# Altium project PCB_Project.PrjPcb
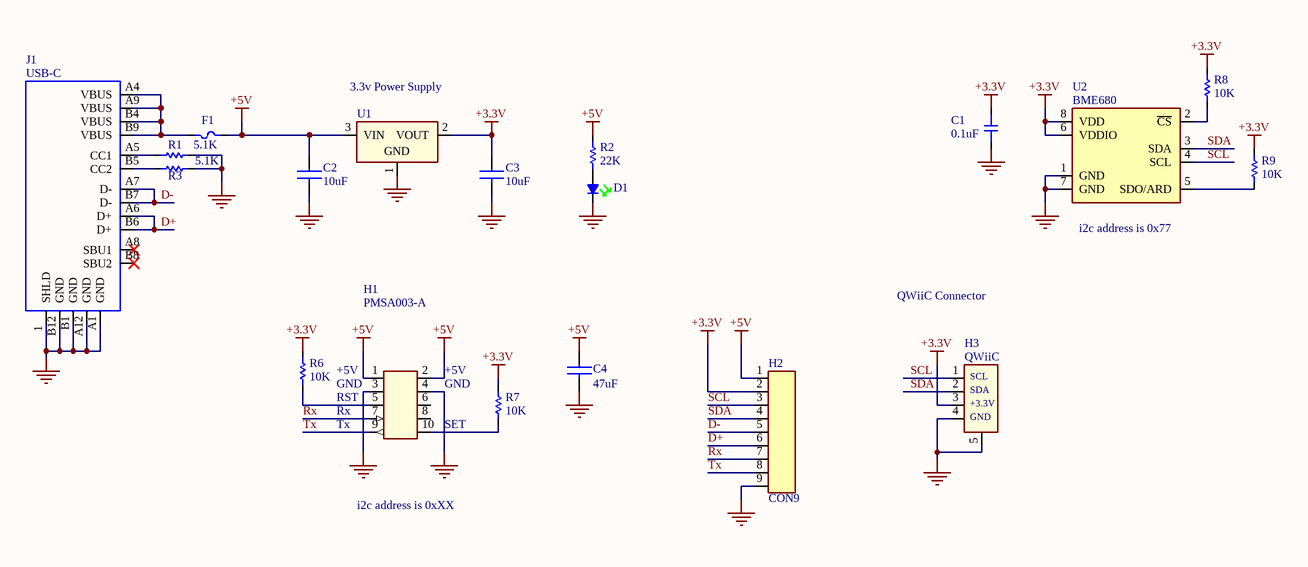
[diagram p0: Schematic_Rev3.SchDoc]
1 sheet, 19 parts. Net scope: global (net labels, ports and power ports of the same name join across sheets).
Board file: PCB_Rev3.PcbDoc

## Sheet Schematic_Rev3.SchDoc: ESP32 Particle Sensor, Sensor
size Tabloid; Organization: .; Address1: @mikerankin; Address2: .; Address3: .; Address4: .; DocumentNumber: .; Revision: 3; SheetNumber: 1; SheetTotal: 1

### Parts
C1  0.1uF  [CAPC1005X56N]
C2  10uF  [CAPC2012X140N]
C3  10uF  [CAPC2012X140N]
C4  47uF  [CAPC3225X160N]
D1  Green Led  [LED1005X40N-Green]  (value not drawn)
F1  TLC-PSMD050  [PTC2012X70L]  (value not drawn)
H1  PMSA003-A  [PMSA003-A]
H2  CON9  [HDR9X1-50MIL]  (no BOM)
H3  QWiiC  [SM04B-SRSS-TB]
J1  USB-C  [TYPE-C-31-M-12]
R1  5.1K  [RESC1005X40L (0402 FOOTPRINT)]
R2  22K  [RESC1005X40L (0402 FOOTPRINT)]
R3  5.1K  [RESC1005X40L (0402 FOOTPRINT)]
R6  10K  [RESC1005X40L (0402 FOOTPRINT)]
R7  10K  [RESC1005X40L (0402 FOOTPRINT)]
R8  10K  [RESC1005X40L (0402 FOOTPRINT)]
R9  10K  [RESC1005X40L (0402 FOOTPRINT)]
U1  NCP1117LPST33T3G  [SOT230P700X180-4N]  (value not drawn)
U2  BME680  [LGA3X3-8N]

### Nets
+3.3V: C1.1 C3.1 H2.2 H3.3 R6.2 R7.2 R8.2 R9.2 U1.2(VOUT) U2.6(VDDIO) U2.8(VDD)
+5V: C2.1 C4.1 F1.1 H1.1(+5V) H1.2(+5V) H2.1 R2.2 U1.3(VIN)
GND: C1.2 C2.2 C3.2 C4.2 D1.1 H1.3 H1.4 H2.9 H3.4 H3.5 J1.1(SHLD) J1.A1(GND) J1.A12(GND) J1.B1(GND) J1.B12(GND) R1.2 R3.2 U1.1(GND) U2.1(GND) U2.7(GND)
D+: H2.6 J1.A6(D+) J1.B6(D+)
D-: H2.5 J1.A7(D-) J1.B7(D-)
Rx: H1.7 H2.7
SCL: H2.3 H3.1 U2.4(SCL)
SDA: H2.4 H3.2 U2.3(SDA)
Tx: H1.9 H2.8
NetD1_2: D1.2 R2.1
NetF1_2: F1.2 J1.A4(VBUS) J1.A9(VBUS) J1.B4(VBUS) J1.B9(VBUS)
NetH1_5: H1.5 R6.1
NetH1_10: H1.10 R7.1
NetJ1_A5: J1.A5(CC1) R1.1
NetJ1_B5: J1.B5(CC2) R3.1
NetR8_1: R8.1 U2.2(~{CS})
NetR9_1: R9.1 U2.5(SDO/ARD)

Not connected (* = marked no-connect by the designer): H1 6 8; J1 A8(SBU1)* B8(SBU2)*

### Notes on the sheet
- (near U1) 3.3v Power Supply
- (near U2) i2c address is 0x77
- QWiiC Connector
- i2c address is 0xXX

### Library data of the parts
C1 = CAP_0402: CAP 0.1uF 0402; Part_Number: C60474; Manufacturer: Yageo; Part_Footprint: 0402; Vendor: LCSC
C2 C3 = CAP_0805: CAP 10uF 0805; Part_Number: C307520; Manufacturer: Samsung; Part_Footprint: 0805; Vendor: LCSC
C4 = CAP_1210: CAP 47uF 1210; Part_Number: C77101; Manufacturer: Murata; Part_Footprint: 1210; Vendor: LCSC
D1 = LED_0402_SMALL_GREEN: LED Green 0402; Part_Number: C74338; Manufacturer: Everlight; Part_Footprint: 0402; Vendor: LCSC
F1 = PTC_FUSE: PTC FUSE 500mA hold, 1A trip 0805 SMD; Manufacturer: TLC; Part_Number: C261942; Part_Footprint: 0805; Vendor: LCSC
H1 = PMSA003-A: Dust Particle Sensor I2C; Manufacturer: Plantower; Part_Number: C132744; Vendor: LCSC
H2 = CON9: CONN HEADER 9POS .100" PADS
H3 = SM04B-SRSS-TB: CONN HEADER 4POS .100 R/A QWIIC; Manufacturer: JST; Part_Number: C160404; Vendor: LCSC
J1 = USB-C: CONN RECPT USB-C; Manufacturer: KHE; Part_Number: C165948; Part_Footprint: SMT; Vendor: LCSC
R1 R3 = RES_0603: RES 5.1K 0402; Manufacturer: Uniroyal; Part_Number: C25905; Part_Footprint: 0402; Vendor: LCSC
R2 = RES_0603: RES 22K 0402; Manufacturer: LIZ Elec; Part_Number: C100310; Part_Footprint: 0402; Vendor: LCSC
R6-R9 = RES_0603: RES 10K 0402; Manufacturer: Guangdong; Part_Number: C258091; Part_Footprint: 0402; Vendor: LCSC
U1 = NCP1117LPST33T3G: IC REG LDO 3.3V 1A SOT223-3; Manufacturer: ON Semi; Part_Number: C146799; Vendor: LCSC; Value: 3.3V 1A LDO
U2 = BME680: Gas, Humidity, Pressure, Temperature Sensor I2C,; Manufacturer: Bosch; Part_Footprint: 8LGA; Vendor: Digi-Key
